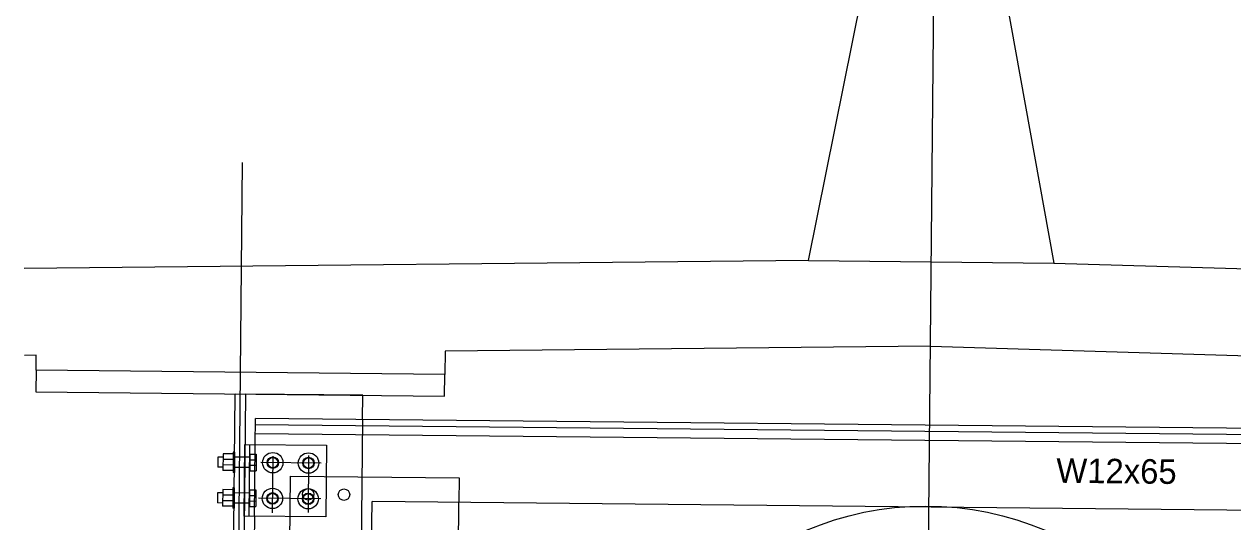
# Model space of a CAD drawing. Extents: x 632312 to 632885, y 378199 to 378534.
# Drawn here: x 632362.35 to 632372.21, y 378392.89 to 378396.95 of the extents above; entities that cross this region are included whole.
import ezdxf

# ---------------------------------------------------------------- set-up
doc = ezdxf.new("R2010")
doc.units = 0
for name, color, linetype in [('B_Boring', 7, 'Continuous'), ('B_Boring Annot', 7, 'Continuous'), ('R_Border', 7, 'Continuous'), ('R_Border_Divider', 7, 'Continuous'), ('R_Proposed Const Limits Cut', 7, 'Continuous'), ('R_Road Edge of Shoulder', 7, 'Continuous'), ('R_Shade Removal', 7, 'Continuous'), ('R_Wall', 7, 'Continuous'), ('SHT_Dimensions', 7, 'Continuous')]:
    doc.layers.add(name, color=color, linetype=linetype)

msp = doc.modelspace()

# ---------------------------------------------------------------- linework, layer by layer
at = {"layer": 'B_Boring'}
for p, q in [((632364.2348, 378393.5156), (632364.2369, 378393.7281)), ((632375.2364, 378393.6187), (632364.2369, 378393.7281)), ((632375.2359, 378393.5683), (632364.2364, 378393.6777)), ((632363.9736, 378393.4401), (632363.9723, 378393.3047)), ((632364.0569, 378393.4392), (632363.9736, 378393.4401)), ((632364.0571, 378393.4549), (632364.0554, 378393.2882)), ((632364.0675, 378393.4548), (632364.0571, 378393.4549)), ((632364.0675, 378393.4548), (632364.0659, 378393.2881)), ((632364.1457, 378392.9331), (632364.1515, 378393.5164)), ((632364.1515, 378393.5164), (632364.8181, 378393.5098)), ((632364.1873, 378392.9327), (632364.1931, 378393.516)), ((632364.1924, 378393.4379), (632364.191, 378393.3025)), ((632364.1924, 378393.4379), (632364.2444, 378393.4374)), ((632364.2444, 378393.4374), (632364.2431, 378393.302)), ((632364.8181, 378393.5098), (632364.8123, 378392.9265)), ((632363.9317, 378393.4144), (632363.9309, 378393.3311)), ((632363.9725, 378393.3307), (632363.9309, 378393.3311)), ((632363.9734, 378393.414), (632363.9317, 378393.4144)), ((632364.0561, 378393.349), (632363.9727, 378393.3498)), ((632364.0565, 378393.3941), (632363.9732, 378393.3949)), ((632364.1915, 378393.3476), (632364.2435, 378393.3471)), ((632364.1919, 378393.3928), (632364.244, 378393.3922)), ((632364.0556, 378393.3038), (632363.9723, 378393.3047)), ((632364.0659, 378393.2881), (632364.0554, 378393.2882)), ((632364.191, 378393.3025), (632364.2431, 378393.302)), ((632365.8988, 378393.2438), (632365.8988, 378393.2438)), ((632363.9707, 378393.1484), (632363.9694, 378393.013)), ((632364.054, 378393.1476), (632363.9707, 378393.1484)), ((632364.0542, 378393.1632), (632364.0525, 378392.9966)), ((632364.0646, 378393.1631), (632364.0542, 378393.1632)), ((632364.0646, 378393.1631), (632364.063, 378392.9965)), ((632364.1895, 378393.1462), (632364.1881, 378393.0108)), ((632364.1895, 378393.1462), (632364.2415, 378393.1457)), ((632364.2415, 378393.1457), (632364.2402, 378393.0103)), ((632363.9288, 378393.1228), (632363.928, 378393.0395)), ((632363.9696, 378393.0391), (632363.928, 378393.0395)), ((632363.9705, 378393.1224), (632363.9288, 378393.1228)), ((632364.0532, 378393.0573), (632363.9698, 378393.0581)), ((632364.0536, 378393.1025), (632363.9703, 378393.1033)), ((632364.1886, 378393.056), (632364.2406, 378393.0555)), ((632364.189, 378393.1011), (632364.2411, 378393.1006)), ((632364.0527, 378393.0122), (632363.9694, 378393.013)), ((632364.063, 378392.9965), (632364.0525, 378392.9966)), ((632364.8123, 378392.9265), (632364.1457, 378392.9331)), ((632364.1881, 378393.0108), (632364.2402, 378393.0103)), ((632364.229, 378392.9323), (632364.2269, 378392.7198))]:
    msp.add_line(p, q, dxfattribs=at)
for points in [[(632365.7805, 378393.9117), (632365.7822, 378394.0888), (632362.4491, 378394.1219), (632362.4473, 378393.9449)], [(632364.0363, 378381.9285), (632363.9529, 378381.9293), (632364.0722, 378393.9287), (632364.1556, 378393.9279)]]:
    msp.add_lwpolyline(points, close=True, dxfattribs=at)
msp.add_lwpolyline([(632365.1119, 378393.7194), (632365.1138, 378393.9183), (632364.1556, 378393.9279), (632364.0363, 378381.9285), (632364.9945, 378381.9189), (632364.9958, 378382.0439)], dxfattribs=at)
for centre in [(632364.3792, 378393.3683), (632364.6708, 378393.3654), (632364.6683, 378393.1102), (632364.9599, 378393.1073), (632364.3763, 378393.0767), (632364.6679, 378393.0738)]:
    msp.add_circle(centre, 0.0469, dxfattribs=at)
at = {"layer": 'B_Boring Annot'}
for p, q in [((632368.7499, 378395.0164), (632369.4514, 378398.5096)), ((632370.118, 378398.503), (632370.7498, 378394.9965)), ((632368.7499, 378395.0164), (632362.3514, 378394.9521)), ((632370.7498, 378394.9965), (632377.1459, 378394.805)), ((632369.7431, 378394.3182), (632365.7841, 378394.2784)), ((632369.7431, 378394.3182), (632373.7004, 378394.1997)), ((632362.4503, 378394.2448), (632362.355, 378394.2439)), ((632362.4491, 378394.1219), (632362.4503, 378394.2448)), ((632365.7841, 378394.2784), (632365.7822, 378394.0888)), ((632365.7822, 378394.0888), (632362.4491, 378394.1219))]:
    msp.add_line(p, q, dxfattribs=at)
at = {"layer": 'R_Border'}
msp.add_circle((632369.7052, 378390.5142), 2.5, dxfattribs=at)
at = {"layer": 'R_Border_Divider'}
msp.add_line((632368.7499, 378395.0164), (632370.7498, 378394.9965), dxfattribs=at)
at = {"layer": 'R_Proposed Const Limits Cut'}
for p, q in [((632365.1119, 378393.7194), (632365.0931, 378391.8351)), ((632375.2351, 378393.4937), (632364.2357, 378393.6031)), ((632364.229, 378392.9323), (632364.2348, 378393.5156)), ((632364.1913, 378393.3285), (632364.0663, 378393.3298)), ((632364.1921, 378393.4119), (632364.0671, 378393.4131)), ((632364.5185, 378392.7169), (632364.5239, 378393.2575)), ((632364.5239, 378393.2575), (632365.8988, 378393.2438)), ((632365.8988, 378393.2438), (632365.8969, 378393.0439)), ((632364.1884, 378393.0369), (632364.0634, 378393.0381)), ((632364.1892, 378393.1202), (632364.0642, 378393.1214)), ((632365.185, 378392.6946), (632365.1886, 378393.0509)), ((632374.2714, 378392.9606), (632365.1886, 378393.0509)), ((632365.8927, 378392.6272), (632365.8969, 378393.0439))]:
    msp.add_line(p, q, dxfattribs=at)
for centre, radius in [((632364.3792, 378393.3683), 0.0833), ((632364.6708, 378393.3654), 0.0833), ((632364.3792, 378393.3683), 0.0417), ((632364.6708, 378393.3654), 0.0417), ((632364.3763, 378393.0767), 0.0833), ((632364.6679, 378393.0738), 0.0833), ((632364.3763, 378393.0767), 0.0417), ((632364.6679, 378393.0738), 0.0417)]:
    msp.add_circle(centre, radius, dxfattribs=at)
at = {"layer": 'R_Road Edge of Shoulder'}
msp.add_line((632369.5749, 378377.4056), (632369.9054, 378410.6473), dxfattribs=at)
at = {"layer": 'R_Shade Removal'}
msp.add_line((632363.9829, 378380.7519), (632364.1327, 378395.8169), dxfattribs=at)
at = {"layer": 'R_Wall'}
for p, q in [((632364.3797, 378393.4225), (632364.3751, 378392.9595)), ((632364.6714, 378393.4259), (632364.6668, 378392.961)), ((632364.775, 378393.3644), (632364.2804, 378393.3693)), ((632364.7721, 378393.0727), (632364.2623, 378393.0778))]:
    msp.add_line(p, q, dxfattribs=at)

# ---------------------------------------------------------------- texts
at = {"layer": 'SHT_Dimensions'}
msp.add_text('W12x65', height=0.2, rotation=359.43036, dxfattribs=at).set_placement((632370.7695, 378393.2045))

doc.saveas('drawing.dxf')
